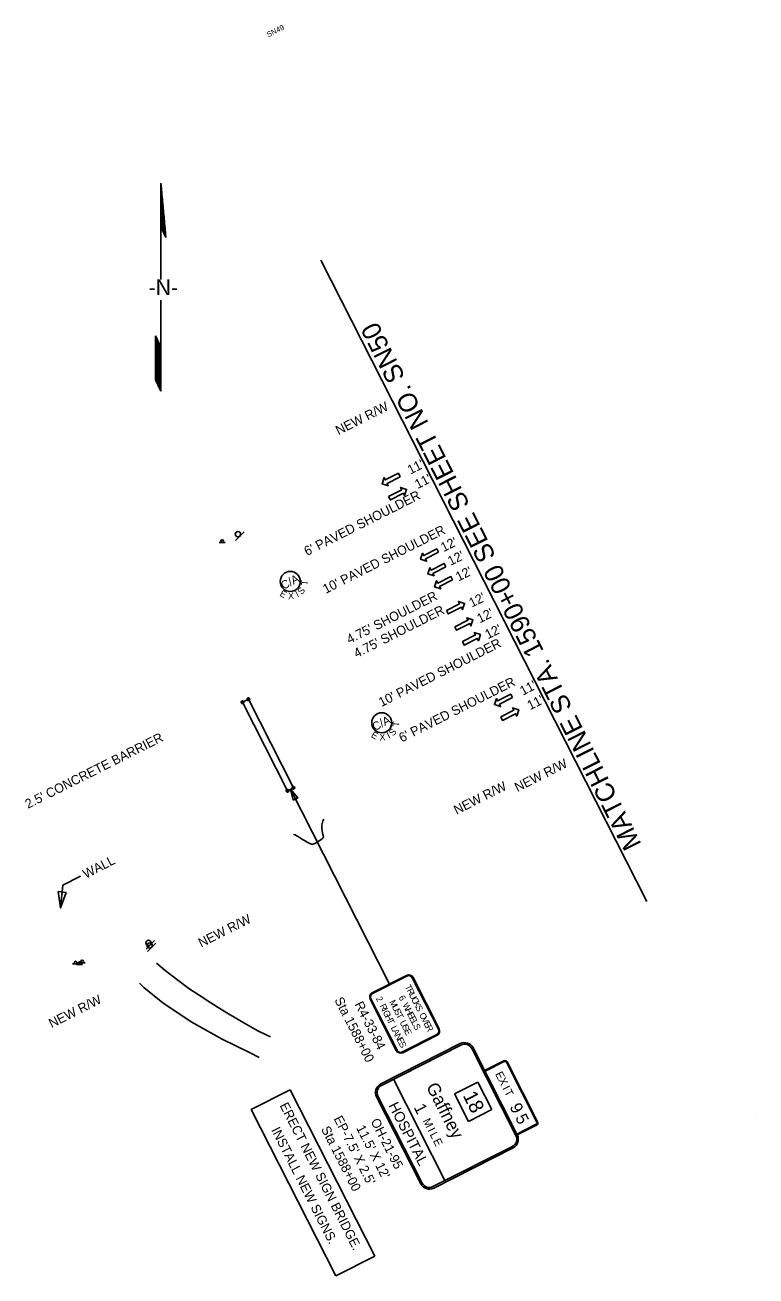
# Model space of a CAD drawing. Extents: x 1804682 to 1806347, y 1188229 to 1189604.
# Drawn here: x 1805800 to 1806347, y 1188666 to 1189604 of the extents above; entities that cross this region are included whole.
import ezdxf

# ---------------------------------------------------------------- set-up
doc = ezdxf.new("R2010")
doc.units = 0
for name, color, linetype in [('RD_EX_Road', 7, 'Continuous'), ('RD_PD_Final_LnLine', 7, 'Continuous'), ('RD_PD_Final_TX', 7, 'Continuous'), ('RD_PD_RW_TX', 7, 'Continuous'), ('RD_SHT_MatchLine', 7, 'Continuous'), ('RD_SHT_TX', 7, 'Continuous'), ('RD_Sketch1', 7, 'Continuous'), ('RD_Sketch8', 7, 'Continuous'), ('SN_P_Signs', 7, 'Continuous'), ('TERMINATOR', 7, 'Continuous')]:
    doc.layers.add(name, color=color, linetype=linetype)

# ---------------------------------------------------------------- blocks, each defined once
blk = doc.blocks.new('SARRW2')
at = {"layer": 'RD_PD_Final_LnLine'}
blk.add_lwpolyline([(-12, 1.2), (-12, -1.2), (-2.83, -1.2), (-2.83, -2.83), (0, 0), (-2.83, 2.83), (-2.83, 1.2)], close=True, dxfattribs=at)

msp = doc.modelspace()

# ---------------------------------------------------------------- linework, layer by layer
at = {"layer": 'RD_EX_Road'}
for points in [[(1806000.92, 1188996.9), (1806002.21, 1188996.68), (1806003.27, 1188996.1), (1806003.94, 1188995.72), (1806006.92, 1188993.83), (1806008.31, 1188992.97), (1806009.32, 1188992.39), (1806011.32, 1188991.29), (1806012.67, 1188990.57), (1806013.7, 1188990.02), (1806014.36, 1188989.66), (1806014.81, 1188989.51), (1806015.54, 1188989.61), (1806016.47, 1188990), (1806017.44, 1188990.48), (1806018.44, 1188991), (1806021.75, 1188993.11), (1806022.48, 1188993.71), (1806023.07, 1188994.25), (1806023.39, 1188995.17), (1806023.19, 1188996.24), (1806022.97, 1188997.07), (1806022.78, 1188998.12), (1806022.32, 1189001.46), (1806022.3, 1189002.79), (1806022.33, 1189003.85), (1806022.47, 1189005.05), (1806022.73, 1189006.27), (1806023.08, 1189007.28), (1806023.37, 1189008.06), (1806023.62, 1189008.43)], [(1805898.42, 1188900.47), (1805904.87, 1188895), (1805914.27, 1188887.76), (1805922.49, 1188881.64), (1805930.29, 1188876.68), (1805939.05, 1188870.8), (1805944.53, 1188867.21), (1805952.23, 1188862.5), (1805963.79, 1188855.79), (1805974.32, 1188849.89), (1805980.47, 1188846.72), (1805983.74, 1188845.28)], [(1805975.4, 1188829.73), (1805967.97, 1188833.58), (1805947.47, 1188843.58), (1805924.37, 1188856.61), (1805903.1, 1188870.71), (1805888.99, 1188882.36), (1805885.67, 1188885.52)]]:
    msp.add_lwpolyline(points, dxfattribs=at)
at = {"layer": 'RD_PD_Final_TX'}
for p, q in [((1805828.33, 1188959.01), (1805826.5, 1188941.94)), ((1805841.56, 1188965.81), (1805828.33, 1188959.01)), ((1806347.37, 1188786.1), (1806347.37, 1188786.1))]:
    msp.add_line(p, q, dxfattribs=at)
at = {"layer": 'RD_SHT_MatchLine'}
msp.add_line((1806021.53, 1189427.49), (1806265.69, 1188946.87), dxfattribs=at)
at = {"layer": 'RD_Sketch1'}
for p, q in [((1805901.74, 1189485.1), (1805901.53, 1189449.93)), ((1805905.46, 1189444.39), (1805901.74, 1189485.1)), ((1805901.74, 1189450.23), (1805901.74, 1189428.4)), ((1805902.04, 1189451.34), (1805905.46, 1189444.39)), ((1805901.74, 1189428.4), (1805901.74, 1189412.93)), ((1805901.74, 1189397.48), (1805901.74, 1189371.71)), ((1805901.74, 1189371.71), (1805901.74, 1189329.19)), ((1805897.75, 1189356.65), (1805897.75, 1189370.82)), ((1805897.75, 1189370.82), (1805901.74, 1189362.26)), ((1805897.75, 1189337.75), (1805897.75, 1189356.65)), ((1805901.74, 1189329.19), (1805897.75, 1189337.75))]:
    msp.add_line(p, q, dxfattribs=at)
for points in [[(1805901.75, 1189450.53), (1805901.75, 1189484.97)], [(1805901.85, 1189450.79), (1805901.85, 1189483.94)], [(1805901.94, 1189451.05), (1805901.94, 1189482.91)], [(1805902.03, 1189451.31), (1805902.03, 1189481.88)], [(1805902.13, 1189451.16), (1805902.13, 1189480.84)], [(1805902.22, 1189450.97), (1805902.22, 1189479.81)], [(1805902.32, 1189450.78), (1805902.32, 1189478.78)], [(1805902.41, 1189450.59), (1805902.41, 1189477.75)], [(1805902.51, 1189450.39), (1805902.51, 1189476.71)], [(1805902.6, 1189450.2), (1805902.6, 1189475.68)], [(1805902.7, 1189450.01), (1805902.7, 1189474.65)], [(1805901.66, 1189450.27), (1805901.66, 1189471.06)], [(1805902.79, 1189449.82), (1805902.79, 1189473.62)], [(1805902.88, 1189449.63), (1805902.88, 1189472.58)], [(1805902.98, 1189449.44), (1805902.98, 1189471.55)], [(1805903.07, 1189449.24), (1805903.07, 1189470.52)], [(1805903.17, 1189449.05), (1805903.17, 1189469.49)], [(1805903.26, 1189448.86), (1805903.26, 1189468.45)], [(1805903.36, 1189448.67), (1805903.36, 1189467.42)], [(1805903.45, 1189448.48), (1805903.45, 1189466.39)], [(1805903.55, 1189448.29), (1805903.55, 1189465.36)], [(1805903.64, 1189448.09), (1805903.64, 1189464.32)], [(1805903.74, 1189447.9), (1805903.74, 1189463.29)], [(1805903.83, 1189447.71), (1805903.83, 1189462.26)], [(1805903.92, 1189447.52), (1805903.92, 1189461.23)], [(1805904.02, 1189447.33), (1805904.02, 1189460.19)], [(1805904.11, 1189447.13), (1805904.11, 1189459.16)], [(1805904.21, 1189446.94), (1805904.21, 1189458.13)], [(1805904.3, 1189446.75), (1805904.3, 1189457.1)], [(1805904.4, 1189446.56), (1805904.4, 1189456.06)], [(1805901.56, 1189450.02), (1805901.56, 1189455.16)], [(1805904.49, 1189446.37), (1805904.49, 1189455.03)], [(1805904.59, 1189446.18), (1805904.59, 1189454)], [(1805904.68, 1189445.98), (1805904.68, 1189452.97)], [(1805904.77, 1189445.79), (1805904.77, 1189451.93)], [(1805904.87, 1189445.6), (1805904.87, 1189450.9)], [(1805904.96, 1189445.41), (1805904.96, 1189449.87)], [(1805905.06, 1189445.22), (1805905.06, 1189448.84)], [(1805905.15, 1189445.03), (1805905.15, 1189447.8)], [(1805905.25, 1189444.83), (1805905.25, 1189446.77)], [(1805905.34, 1189444.64), (1805905.34, 1189445.74)], [(1805905.44, 1189444.45), (1805905.44, 1189444.71)], [(1805897.82, 1189337.59), (1805897.82, 1189370.66)], [(1805897.92, 1189337.39), (1805897.92, 1189370.46)], [(1805898.01, 1189337.18), (1805898.01, 1189370.25)], [(1805898.11, 1189336.98), (1805898.11, 1189370.05)], [(1805898.2, 1189336.78), (1805898.2, 1189369.85)], [(1805898.3, 1189336.58), (1805898.3, 1189369.65)], [(1805898.39, 1189336.37), (1805898.39, 1189369.44)], [(1805898.49, 1189336.17), (1805898.49, 1189369.24)], [(1805898.58, 1189335.97), (1805898.58, 1189369.04)], [(1805898.67, 1189335.76), (1805898.67, 1189368.84)], [(1805898.77, 1189335.56), (1805898.77, 1189368.63)], [(1805898.86, 1189335.36), (1805898.86, 1189368.43)], [(1805898.96, 1189335.16), (1805898.96, 1189368.23)], [(1805899.05, 1189334.95), (1805899.05, 1189368.03)], [(1805899.15, 1189334.75), (1805899.15, 1189367.82)], [(1805899.24, 1189334.55), (1805899.24, 1189367.62)], [(1805899.34, 1189334.35), (1805899.34, 1189367.42)], [(1805899.43, 1189334.14), (1805899.43, 1189367.21)], [(1805899.52, 1189333.94), (1805899.52, 1189367.01)], [(1805899.62, 1189333.74), (1805899.62, 1189366.81)], [(1805899.71, 1189333.54), (1805899.71, 1189366.61)], [(1805899.81, 1189333.33), (1805899.81, 1189366.4)], [(1805899.9, 1189333.13), (1805899.9, 1189366.2)], [(1805900, 1189332.93), (1805900, 1189366)], [(1805900.09, 1189332.73), (1805900.09, 1189365.8)], [(1805900.19, 1189332.52), (1805900.19, 1189365.59)], [(1805900.28, 1189332.32), (1805900.28, 1189365.39)], [(1805900.37, 1189332.12), (1805900.37, 1189365.19)], [(1805900.47, 1189331.92), (1805900.47, 1189364.99)], [(1805900.56, 1189331.71), (1805900.56, 1189364.78)], [(1805900.66, 1189331.51), (1805900.66, 1189364.58)], [(1805900.75, 1189331.31), (1805900.75, 1189364.38)], [(1805900.85, 1189331.1), (1805900.85, 1189364.18)], [(1805900.94, 1189330.9), (1805900.94, 1189363.97)], [(1805901.04, 1189330.7), (1805901.04, 1189363.77)], [(1805901.13, 1189330.5), (1805901.13, 1189363.57)], [(1805901.23, 1189330.29), (1805901.23, 1189363.36)], [(1805901.32, 1189330.09), (1805901.32, 1189363.16)], [(1805901.41, 1189329.89), (1805901.41, 1189362.96)], [(1805901.51, 1189329.69), (1805901.51, 1189362.76)], [(1805901.6, 1189329.48), (1805901.6, 1189362.55)], [(1805901.7, 1189329.28), (1805901.7, 1189362.35)]]:
    msp.add_lwpolyline(points, dxfattribs=at)
at = {"layer": 'RD_Sketch8'}
for centre in [(1805998.57, 1189186.62), (1806067.06, 1189080.7)]:
    msp.add_circle(centre, 7.5, dxfattribs=at)
at = {"layer": 'SN_P_Signs'}
for p, q in [((1805957.65, 1189217.43), (1805964.01, 1189223.8)), ((1805945.36, 1189215.81), (1805949.86, 1189215.81)), ((1805966.87, 1189097.42), (1805967.49, 1189099.32)), ((1805961.81, 1189096.43), (1805963.71, 1189095.81)), ((1805962.45, 1189095.18), (1805963.07, 1189097.07)), ((1805967.18, 1189098.37), (1805962.76, 1189096.12)), ((1805962.76, 1189096.12), (1805996.5, 1189029.7)), ((1805966.23, 1189098.68), (1805968.13, 1189098.06)), ((1806000.92, 1189031.95), (1805967.18, 1189098.37)), ((1805995.55, 1189030.01), (1805997.45, 1189029.39)), ((1805996.19, 1189028.76), (1805996.81, 1189030.65)), ((1805996.5, 1189029.7), (1806000.92, 1189031.95)), ((1806072.85, 1188884.9), (1805998.71, 1189030.83)), ((1805999.97, 1189032.26), (1806001.87, 1189031.64)), ((1806000.61, 1189031), (1806001.23, 1189032.9)), ((1805890.61, 1188911.1), (1805896.97, 1188917.46)), ((1805891.58, 1188909.18), (1805897.94, 1188915.54)), ((1805835.59, 1188899.94), (1805840.09, 1188899.94)), ((1805838.56, 1188899.58), (1805843.06, 1188899.58)), ((1805840.54, 1188900.75), (1805845.04, 1188900.75)), ((1806121.55, 1188802.54), (1806139.1, 1188811.46)), ((1805969.32, 1188790.88), (1805998.57, 1188805.74)), ((1805998.57, 1188805.74), (1806061.96, 1188680.96)), ((1806097.37, 1188735.69), (1806064.25, 1188800.87)), ((1806032.71, 1188666.11), (1805969.32, 1188790.88)), ((1806149.55, 1188790.89), (1806132, 1188781.97)), ((1806061.96, 1188680.96), (1806032.71, 1188666.11))]:
    msp.add_line(p, q, dxfattribs=at)
for points in [[(1805967.63, 1189097.48), (1805967.48, 1189097.41), (1805967.31, 1189097.38), (1805967.15, 1189097.37), (1805966.98, 1189097.39), (1805966.82, 1189097.43), (1805966.67, 1189097.51), (1805966.53, 1189097.6), (1805966.42, 1189097.72), (1805966.32, 1189097.86), (1805966.25, 1189098.01), (1805966.2, 1189098.17), (1805966.18, 1189098.33), (1805966.19, 1189098.5), (1805966.22, 1189098.66), (1805966.29, 1189098.82), (1805966.37, 1189098.96), (1805966.48, 1189099.09), (1805966.61, 1189099.19), (1805966.73, 1189099.26)], [(1805966.73, 1189099.26), (1805966.88, 1189099.32), (1805967.04, 1189099.36), (1805967.21, 1189099.37), (1805967.38, 1189099.35), (1805967.54, 1189099.3), (1805967.69, 1189099.23), (1805967.82, 1189099.13), (1805967.94, 1189099.02), (1805968.04, 1189098.88), (1805968.11, 1189098.73), (1805968.16, 1189098.57), (1805968.18, 1189098.4), (1805968.17, 1189098.24), (1805968.13, 1189098.07), (1805968.07, 1189097.92), (1805967.98, 1189097.78), (1805967.88, 1189097.65), (1805967.75, 1189097.55), (1805967.63, 1189097.48)], [(1805963.21, 1189095.23), (1805963.06, 1189095.17), (1805962.9, 1189095.13), (1805962.73, 1189095.12), (1805962.56, 1189095.14), (1805962.4, 1189095.19), (1805962.25, 1189095.26), (1805962.12, 1189095.36), (1805962, 1189095.48), (1805961.9, 1189095.61), (1805961.83, 1189095.76), (1805961.78, 1189095.92), (1805961.76, 1189096.09), (1805961.77, 1189096.26), (1805961.8, 1189096.42), (1805961.87, 1189096.57), (1805961.95, 1189096.72), (1805962.06, 1189096.84), (1805962.19, 1189096.95), (1805962.31, 1189097.02)], [(1805962.31, 1189097.02), (1805962.46, 1189097.08), (1805962.63, 1189097.12), (1805962.79, 1189097.12), (1805962.96, 1189097.1), (1805963.12, 1189097.06), (1805963.27, 1189096.99), (1805963.41, 1189096.89), (1805963.52, 1189096.77), (1805963.62, 1189096.64), (1805963.69, 1189096.48), (1805963.74, 1189096.33), (1805963.76, 1189096.16), (1805963.75, 1189095.99), (1805963.72, 1189095.83), (1805963.65, 1189095.67), (1805963.57, 1189095.53), (1805963.46, 1189095.41), (1805963.33, 1189095.3), (1805963.21, 1189095.23)], [(1805996.96, 1189028.81), (1805996.8, 1189028.75), (1805996.64, 1189028.71), (1805996.47, 1189028.7), (1805996.31, 1189028.72), (1805996.15, 1189028.77), (1805995.99, 1189028.84), (1805995.86, 1189028.94), (1805995.74, 1189029.06), (1805995.64, 1189029.19), (1805995.57, 1189029.34), (1805995.52, 1189029.5), (1805995.5, 1189029.67), (1805995.51, 1189029.84), (1805995.55, 1189030), (1805995.61, 1189030.15), (1805995.7, 1189030.3), (1805995.81, 1189030.42), (1805995.94, 1189030.53), (1805996.05, 1189030.6)], [(1805996.05, 1189030.6), (1805996.21, 1189030.66), (1805996.37, 1189030.7), (1805996.54, 1189030.7), (1805996.7, 1189030.68), (1805996.86, 1189030.64), (1805997.01, 1189030.56), (1805997.15, 1189030.47), (1805997.27, 1189030.35), (1805997.36, 1189030.22), (1805997.44, 1189030.06), (1805997.48, 1189029.9), (1805997.5, 1189029.74), (1805997.5, 1189029.57), (1805997.46, 1189029.41), (1805997.4, 1189029.25), (1805997.31, 1189029.11), (1805997.2, 1189028.99), (1805997.07, 1189028.88), (1805996.96, 1189028.81)], [(1806001.37, 1189031.06), (1806001.22, 1189030.99), (1806001.06, 1189030.96), (1806000.89, 1189030.95), (1806000.72, 1189030.97), (1806000.56, 1189031.01), (1806000.41, 1189031.09), (1806000.28, 1189031.18), (1806000.16, 1189031.3), (1806000.06, 1189031.44), (1805999.99, 1189031.59), (1805999.94, 1189031.75), (1805999.92, 1189031.91), (1805999.93, 1189032.08), (1805999.97, 1189032.24), (1806000.03, 1189032.4), (1806000.12, 1189032.54), (1806000.23, 1189032.67), (1806000.35, 1189032.77), (1806000.47, 1189032.84)], [(1806000.47, 1189032.84), (1806000.62, 1189032.9), (1806000.79, 1189032.94), (1806000.95, 1189032.95), (1806001.12, 1189032.93), (1806001.28, 1189032.88), (1806001.43, 1189032.81), (1806001.57, 1189032.71), (1806001.68, 1189032.6), (1806001.78, 1189032.46), (1806001.85, 1189032.31), (1806001.9, 1189032.15), (1806001.92, 1189031.98), (1806001.91, 1189031.82), (1806001.88, 1189031.65), (1806001.81, 1189031.5), (1806001.73, 1189031.36), (1806001.62, 1189031.23), (1806001.49, 1189031.13), (1806001.37, 1189031.06)], [(1806085.68, 1188891.42), (1806060.01, 1188878.38)], [(1806085.96, 1188890.89), (1806060.28, 1188877.84)], [(1806109.56, 1188851.06), (1806089.99, 1188889.57)], [(1806110.09, 1188851.33), (1806090.52, 1188889.85)], [(1806058.43, 1188873.54), (1806077.99, 1188835.02)], [(1806058.96, 1188873.81), (1806078.53, 1188835.3)], [(1806082.56, 1188833.98), (1806108.24, 1188847.03)], [(1806082.84, 1188833.45), (1806108.51, 1188846.49)], [(1806066.34, 1188810.01), (1806125.83, 1188840.23)], [(1806066.89, 1188808.94), (1806126.37, 1188839.16)], [(1806135.51, 1188837.07), (1806168.62, 1188771.88)], [(1806134.44, 1188836.52), (1806167.55, 1188771.34)], [(1806158.88, 1188826.83), (1806144.44, 1188819.49), (1806144.16, 1188820.03), (1806158.61, 1188827.36)], [(1806183.32, 1188781.37), (1806160.49, 1188826.3)], [(1806161.03, 1188826.58), (1806183.85, 1188781.64)], [(1806075.87, 1188813.5), (1806114.42, 1188737.62)], [(1806139.1, 1188811.46), (1806149.55, 1188790.89)], [(1806096.3, 1188735.14), (1806063.18, 1188800.33)], [(1806132, 1188781.97), (1806121.55, 1188802.54)], [(1806168.35, 1188772.42), (1806182.79, 1188779.76)], [(1806183.07, 1188779.22), (1806168.62, 1188771.88), (1806168.35, 1188772.42)], [(1806164.92, 1188763.27), (1806105.44, 1188733.05)], [(1806165.46, 1188762.2), (1806105.98, 1188731.98)]]:
    msp.add_lwpolyline(points, dxfattribs=at)
msp.add_lwpolyline([(1806000.69, 1189022.61), (1805998.71, 1189030.83), (1806004.33, 1189024.51)], close=True, dxfattribs=at)
for centre, radius in [((1805959.41, 1189222.06), 2), ((1805947.62, 1189216.82), 1), ((1805892.37, 1188915.72), 2), ((1805893.34, 1188913.81), 2), ((1805842.8, 1188901.76), 1), ((1805837.85, 1188900.95), 1), ((1805840.82, 1188900.59), 1)]:
    msp.add_circle(centre, radius, dxfattribs=at)
for centre, radius, start, end in [((1806087.31, 1188888.21), 3.6, 26.93166, 116.93166), ((1806087.31, 1188888.21), 3, 26.93166, 116.93166), ((1806061.64, 1188875.17), 3.6, 116.93166, 206.93166), ((1806061.64, 1188875.17), 3, 116.93166, 206.93166), ((1806106.88, 1188849.7), 3, 296.93166, 26.93166), ((1806106.88, 1188849.7), 3.6, 296.93166, 26.93166), ((1806129.09, 1188833.81), 7.2, 26.93166, 116.93166), ((1806129.09, 1188833.81), 6, 26.93166, 116.93166), ((1806081.2, 1188836.66), 3.6, 206.93166, 296.93166), ((1806081.2, 1188836.66), 3, 206.93166, 296.93166), ((1806159.42, 1188825.76), 1.8, 26.93166, 116.93166), ((1806159.42, 1188825.76), 1.2, 26.93166, 116.93166), ((1806069.6, 1188803.59), 7.2, 116.93166, 206.93166), ((1806069.6, 1188803.59), 6, 116.93166, 206.93166), ((1806182.25, 1188780.83), 1.2, 296.93166, 26.93166), ((1806182.25, 1188780.83), 1.8, 296.93166, 26.93166), ((1806162.2, 1188768.62), 6, 296.93166, 26.93166), ((1806162.2, 1188768.62), 7.2, 296.93166, 26.93166), ((1806102.72, 1188738.4), 7.2, 206.93166, 296.93166), ((1806102.72, 1188738.4), 6, 206.93166, 296.93166)]:
    msp.add_arc(centre, radius, start, end, dxfattribs=at)
at = {"layer": 'TERMINATOR'}
msp.add_lwpolyline([(1805830.76, 1188953.55), (1805826.5, 1188941.94), (1805824.79, 1188954.19)], close=True, dxfattribs=at)

# ---------------------------------------------------------------- block references
at = {"layer": 'RD_PD_Final_LnLine'}
for p, xscale, yscale, rotation in [((1806067.37, 1189259.9), 1.1999999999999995, 1.2000000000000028, -153.06833411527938), ((1806085.71, 1189255.58), 1.1999999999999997, 1.2000000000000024, 26.931665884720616), ((1806096.16, 1189203.23), 1.1999999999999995, 1.2000000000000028, -153.06833411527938), ((1806101.69, 1189192.33), 1.1999999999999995, 1.2000000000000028, -153.06833411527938), ((1806106.67, 1189182.53), 1.1999999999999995, 1.2000000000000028, -153.06833411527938), ((1806129.13, 1189170.13), 1.1999999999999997, 1.2000000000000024, 26.931665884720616), ((1806135.36, 1189157.85), 1.1999999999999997, 1.2000000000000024, 26.931665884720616), ((1806140.99, 1189146.78), 1.1999999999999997, 1.2000000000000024, 26.931665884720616), ((1806151.49, 1189094.31), 1.1999999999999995, 1.2000000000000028, -153.06833411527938), ((1806169.68, 1189090.31), 1.1999999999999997, 1.2000000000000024, 26.931665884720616)]:
    msp.add_blockref('SARRW2', p, dxfattribs=dict(at, xscale=xscale, yscale=yscale, rotation=rotation))

# ---------------------------------------------------------------- texts
at = {"layer": 'RD_PD_Final_TX'}
for s, rotation, p in [("11'", 27.18166, (1806088.55, 1189266.6)), ("11'", 27.18166, (1806094.03, 1189255.81)), ("6' PAVED SHOULDER", 26.81776, (1806011.13, 1189205.65)), ("10' PAVED SHOULDER", 26.81776, (1806025.13, 1189177.28)), ("12'", 26.30484, (1806113.38, 1189208.56)), ("12'", 26.30484, (1806118.61, 1189198.27)), ("12'", 26.30484, (1806124.56, 1189186.54)), ("4.75' SHOULDER", 26.93166, (1806042.93, 1189139.66)), ("12'", 26.30484, (1806134.51, 1189166.98)), ("4.75' SHOULDER", 26.93166, (1806048.27, 1189129.14)), ("12'", 26.30484, (1806140.49, 1189155.2)), ("12'", 26.30484, (1806146.57, 1189143.23)), ("10' PAVED SHOULDER", 26.81776, (1806066.96, 1189092.46)), ("6' PAVED SHOULDER", 26.81776, (1806082.15, 1189065.85)), ("11'", 27.18166, (1806172.7, 1189100.96)), ("11'", 27.18166, (1806178.24, 1189090.05)), ("2.5' CONCRETE BARRIER", 26.6834, (1805802.14, 1189016.15)), ('WALL', 27.18166, (1805845.44, 1188963.76))]:
    msp.add_text(s, height=7, rotation=rotation, dxfattribs=at).set_placement(p)
at = {"layer": 'RD_PD_RW_TX'}
for p in [(1806034.74, 1189296.2), (1806168.77, 1189028.71), (1806123.2, 1189011.74), (1805931.84, 1188912.14), (1805819.86, 1188851.78)]:
    msp.add_text('NEW R/W', height=7, rotation=26.75486, dxfattribs=at).set_placement(p)
at = {"layer": 'RD_SHT_TX'}
for s, height, rotation, p in [('SN49', 4, 26.93166, (1805982.15, 1189594.37)), ('MATCHLINE STA. 1590+00 SEE SHEET NO. SN50', 14.1726, 116.81304, (1806261.9, 1188989.72))]:
    msp.add_text(s, height=height, rotation=rotation, dxfattribs=at).set_placement(p)
at = {"layer": 'RD_Sketch1'}
msp.add_text('-N-', height=11.811, rotation=0, dxfattribs=at).set_placement((1805892.54, 1189401.19))
at = {"layer": 'RD_Sketch8'}
for s, height, rotation, p in [('C/A', 6.25, 26.93166, (1805993.45, 1189180.34)), ('T', 5, 85.11681, (1806011.6, 1189183.47)), ('E', 5, 330.14291, (1805990.18, 1189176.16)), ('X', 5, 2.57228, (1805997, 1189173.29)), ('I', 5, 26.73228, (1806003.99, 1189174.51)), ('S', 5, 48.72411, (1806007.16, 1189176.32)), ('C/A', 6.25, 26.93166, (1806061.93, 1189074.42)), ('T', 5, 85.11681, (1806080.09, 1189077.55)), ('E', 5, 330.14291, (1806058.66, 1189070.24)), ('X', 5, 2.57228, (1806065.48, 1189067.37)), ('I', 5, 26.73228, (1806072.47, 1189068.59)), ('S', 5, 48.72411, (1806075.65, 1189070.4))]:
    msp.add_text(s, height=height, rotation=rotation, dxfattribs=at).set_placement(p)
at = {"layer": 'SN_P_Signs'}
for s, height, rotation, p in [('T', 4.8, 296.93166, (1806084.23, 1188883.02)), ('Sta 1588+00', 7, 296.93175, (1806031.47, 1188873.02)), ('2', 4.8, 296.93166, (1806062.5, 1188874.13)), ('6', 4.8, 296.93166, (1806079.59, 1188874.94)), ('R', 4.8, 296.93166, (1806085.69, 1188880.16)), ('U', 4.8, 296.93166, (1806087.33, 1188876.92)), ('C', 4.8, 296.93166, (1806088.98, 1188873.68)), ('R4-33-84', 7, 296.93175, (1806046.5, 1188869.71)), ('R', 4.8, 296.93166, (1806065.32, 1188868.58)), ('I', 4.8, 296.93166, (1806066.97, 1188865.34)), ('G', 4.8, 296.93166, (1806067.73, 1188863.84)), ('M', 4.8, 296.93166, (1806072.56, 1188871.56)), ('U', 4.8, 296.93166, (1806074.43, 1188867.88)), ('S', 4.8, 296.93166, (1806076.07, 1188864.64)), ('W', 4.8, 296.93166, (1806082.41, 1188869.39)), ('H', 4.8, 296.93166, (1806084.41, 1188865.46)), ('K', 4.8, 296.93166, (1806090.54, 1188870.61)), ('S', 4.8, 296.93166, (1806092.09, 1188867.55)), ('H', 4.8, 296.93166, (1806069.38, 1188860.6)), ('T', 4.8, 296.93166, (1806070.93, 1188857.54)), ('T', 4.8, 296.93166, (1806077.63, 1188861.58)), ('U', 4.8, 296.93166, (1806080.35, 1188856.23)), ('E', 4.8, 296.93166, (1806086.05, 1188862.22)), ('E', 4.8, 296.93166, (1806087.51, 1188859.35)), ('L', 4.8, 296.93166, (1806088.96, 1188856.49)), ('O', 4.8, 296.93166, (1806094.91, 1188862)), ('V', 4.8, 296.93166, (1806096.54, 1188858.8)), ('E', 4.8, 296.93166, (1806098.23, 1188855.47)), ('L', 4.8, 296.93166, (1806073.65, 1188852.19)), ('A', 4.8, 296.93166, (1806074.86, 1188849.8)), ('N', 4.8, 296.93166, (1806076.59, 1188846.41)), ('S', 4.8, 296.93166, (1806081.99, 1188852.99)), ('E', 4.8, 296.93166, (1806083.64, 1188849.75)), ('S', 4.8, 296.93166, (1806090.42, 1188853.63)), ('R', 4.8, 296.93166, (1806099.68, 1188852.61)), ('E', 4.8, 296.93166, (1806078.23, 1188843.17)), ('S', 4.8, 296.93166, (1806079.69, 1188840.3)), ('E', 6, 296.93166, (1806151.84, 1188817.5)), ('Gaffney', 9.6, 296.93166, (1806100.11, 1188808.06)), ('X', 6, 296.93166, (1806154.18, 1188812.9)), ('I', 6, 296.93166, (1806157.26, 1188806.83)), ('18', 10.8, 296.93166, (1806127.54, 1188801.42)), ('T', 6, 296.93166, (1806158.61, 1188804.17)), ('ERECT NEW SIGN BRIDGE.', 7, 296.93175, (1805990.45, 1188794.01)), ('HOSPITAL', 7.8, 296.93166, (1806071.9, 1188793.95)), ('1', 9, 296.93166, (1806090.82, 1188792.55)), ('9', 9, 296.93166, (1806162.65, 1188792.91)), ("EP-7.5' X 2.5'", 7, 296.93175, (1806030.89, 1188784.04)), ('OH-21-95', 7, 296.93175, (1806058.57, 1188782.09)), ('M', 6, 296.93166, (1806097.66, 1188782.41)), ('5', 9, 296.93166, (1806166.78, 1188784.79)), ('INSTALL NEW SIGNS.', 7, 296.93175, (1805984.12, 1188775.56)), ('Sta 1588+00', 7, 296.93175, (1806021.48, 1188776.29)), ("11.5' X 12'", 7, 296.93175, (1806047.76, 1188777.09)), ('I', 6, 296.93166, (1806101.22, 1188775.4)), ('L', 6, 296.93166, (1806102.85, 1188772.19)), ('E', 6, 296.93166, (1806105.3, 1188767.36))]:
    msp.add_text(s, height=height, rotation=rotation, dxfattribs=at).set_placement(p)

doc.saveas('drawing.dxf')
